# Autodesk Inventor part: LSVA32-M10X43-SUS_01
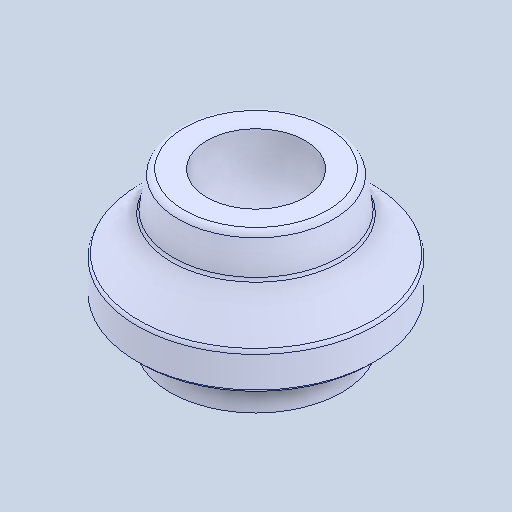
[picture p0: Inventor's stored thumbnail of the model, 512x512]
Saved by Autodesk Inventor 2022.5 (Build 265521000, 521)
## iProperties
Created: 2024-08
Part Number: LSVA32-M10X43-SUS_01
Material: 一般
Document SubType Name: Modeling
Designer: ImaoCorp
Density: 1 g/cm^3
Appearance: 既定
Author: ImaoCorp
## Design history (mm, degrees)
feature "LSVA32-M10X43-SUS_01"
node "ソリッド1"
